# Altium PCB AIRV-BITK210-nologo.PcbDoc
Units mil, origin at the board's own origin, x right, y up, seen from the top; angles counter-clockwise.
Board outline 2559.06 x 1181.1 mil, 4 copper layers (Top Layer, GND, MidLayer1, Bottom Layer), stack 28.8 mil thick; 57 components, 83 nets, 310 pads, 220 vias.
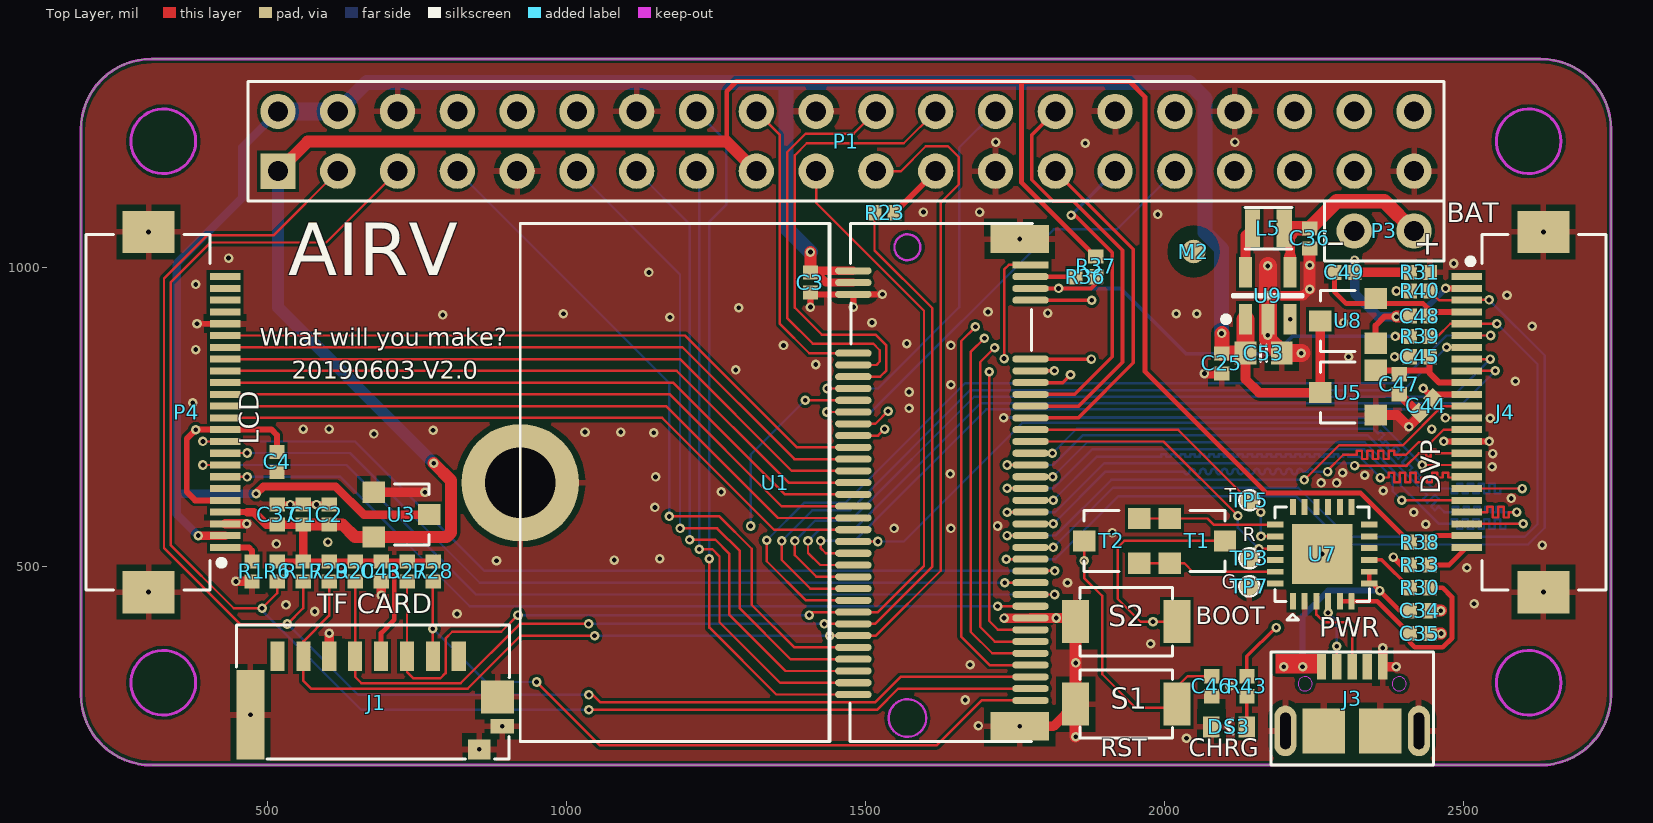
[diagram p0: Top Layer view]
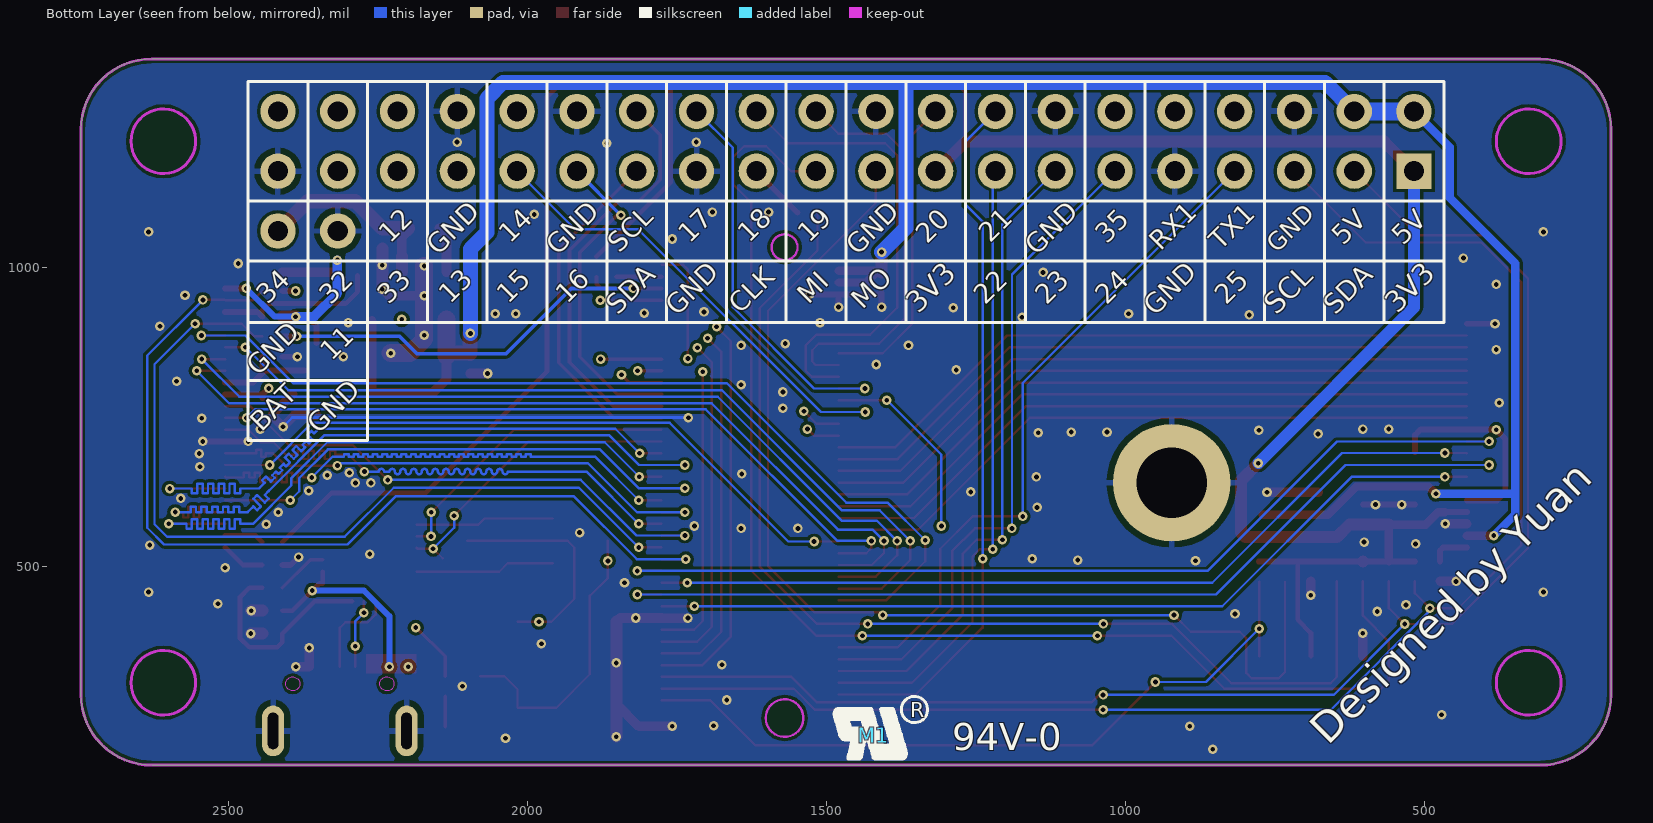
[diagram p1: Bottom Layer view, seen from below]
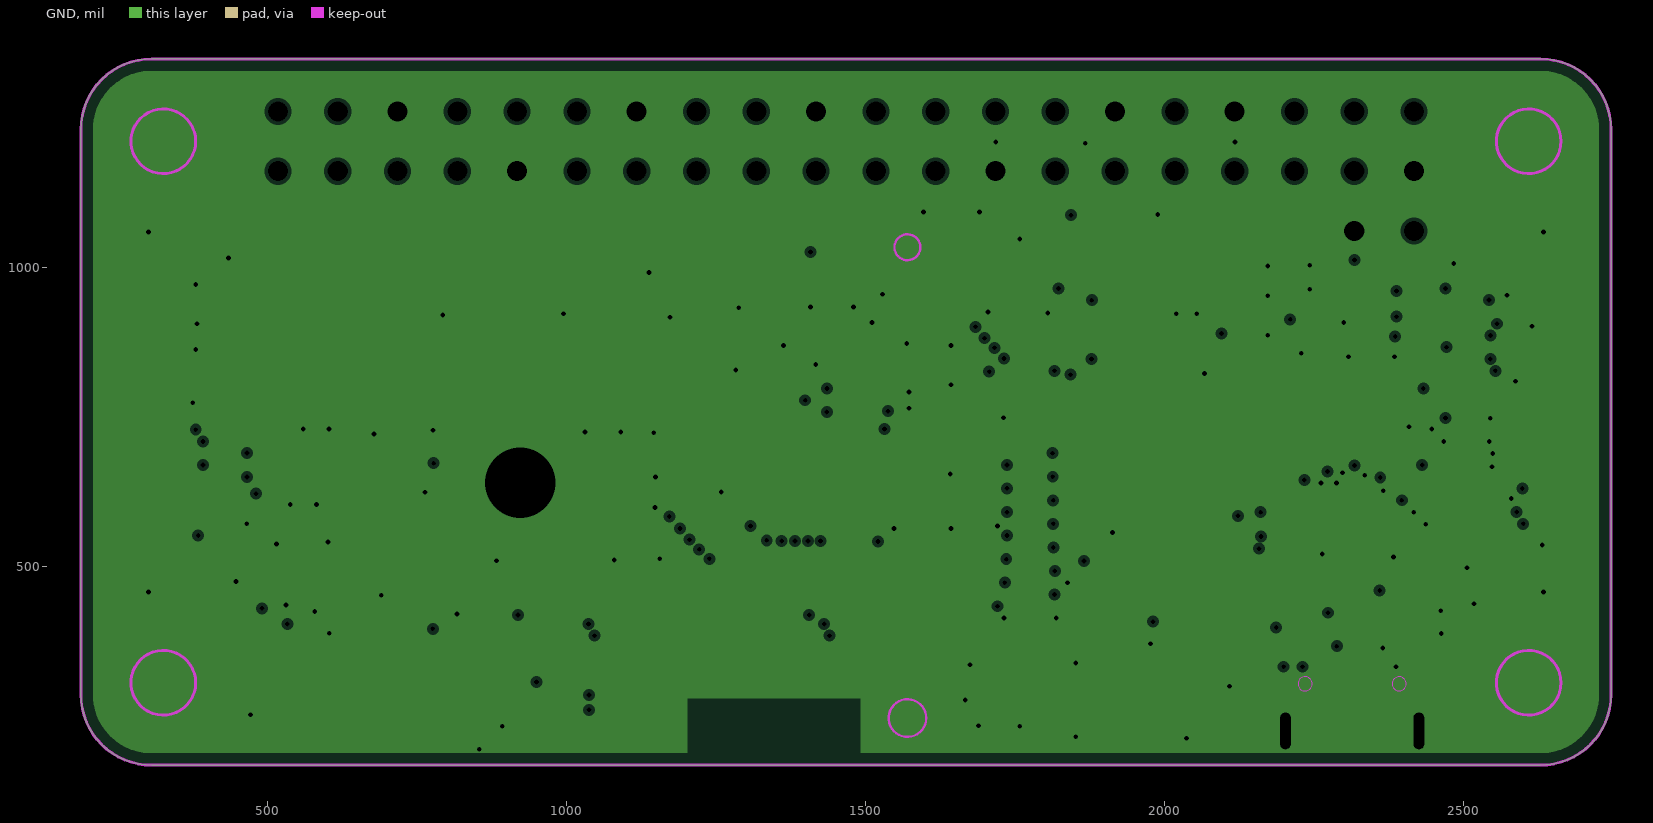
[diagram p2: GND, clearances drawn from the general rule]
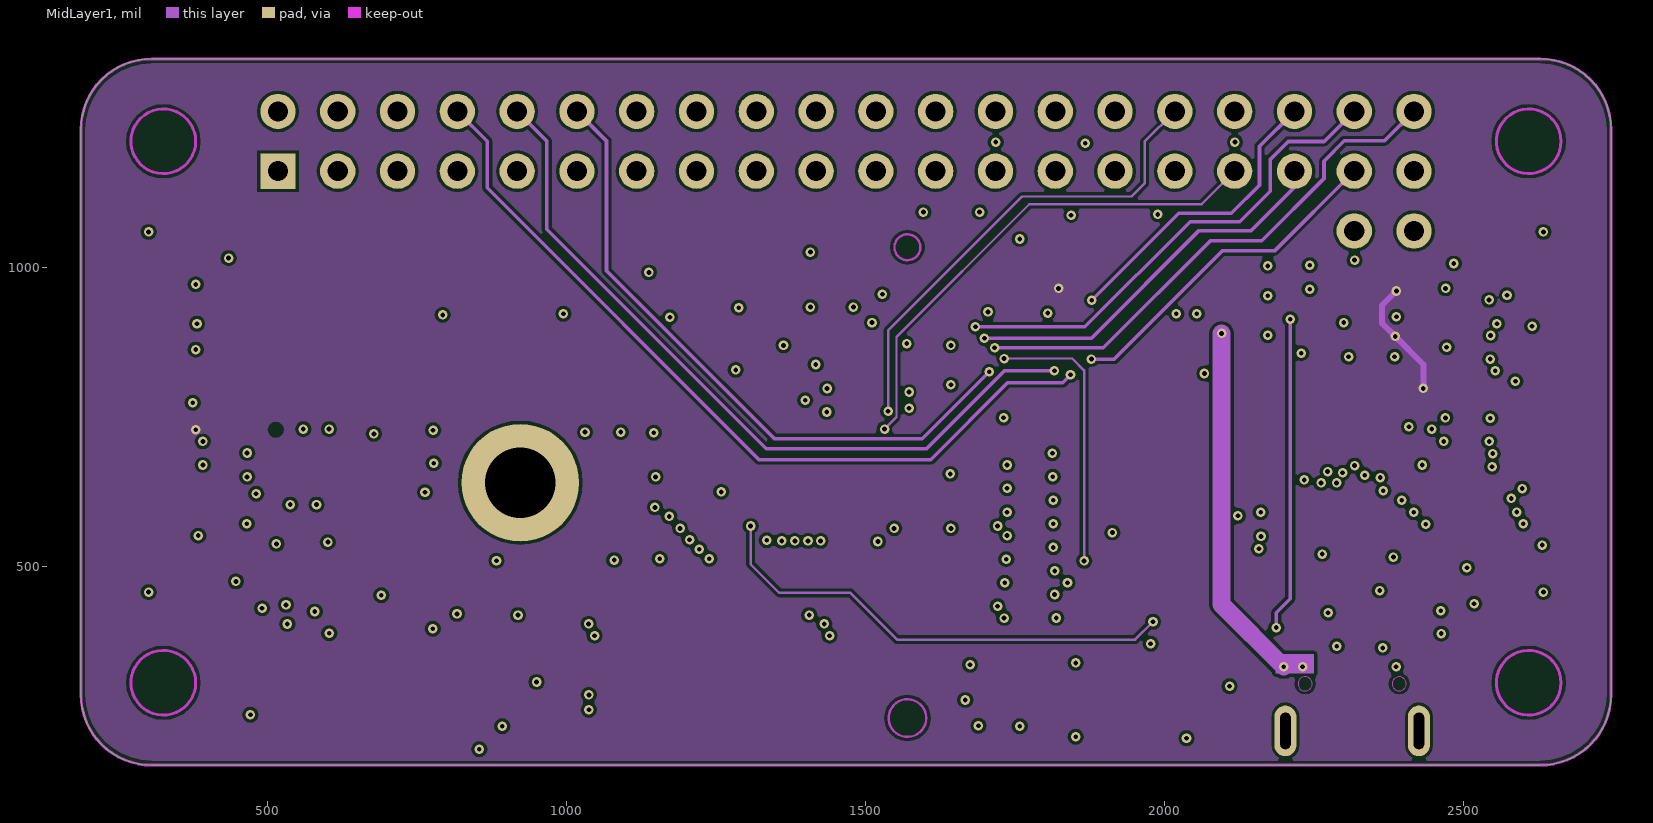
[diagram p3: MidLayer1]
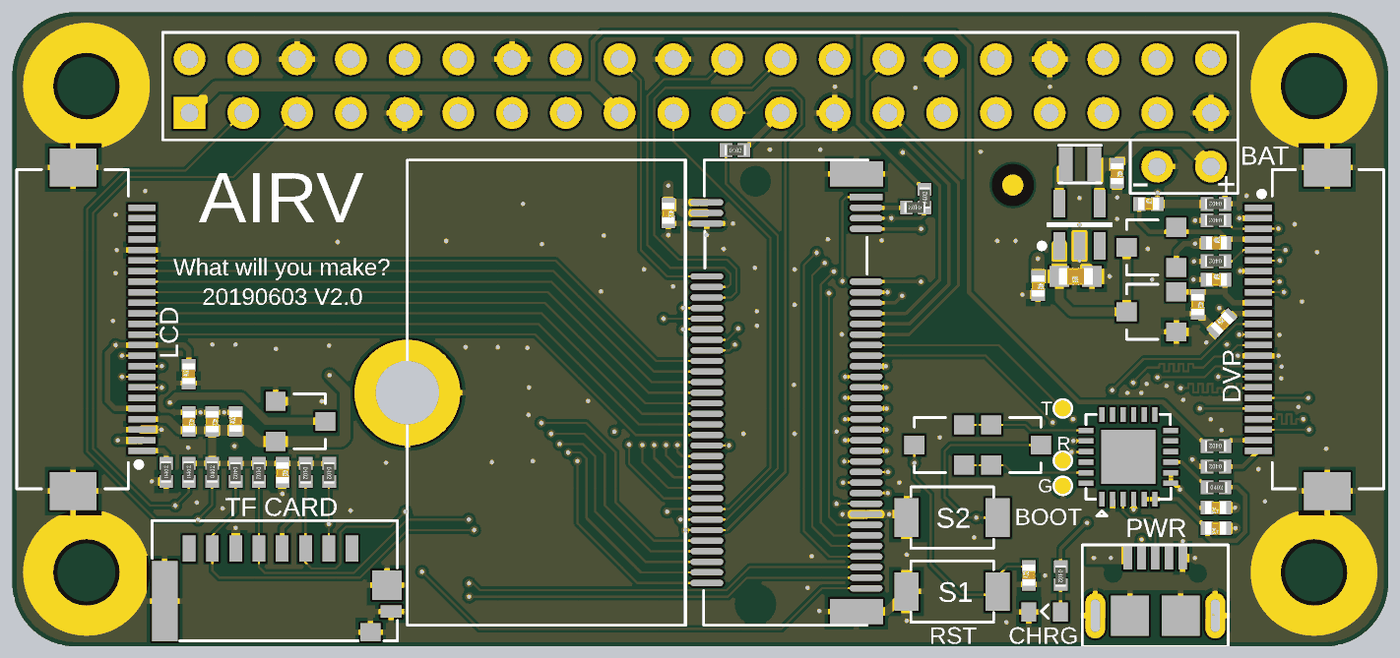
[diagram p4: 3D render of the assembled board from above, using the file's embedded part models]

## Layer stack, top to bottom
Top Solder: solder mask 0.4, Solder Resist, Dk 3.5
Top Layer: signal copper 1.4
Dielectric1: core 7.6, FR-4, Dk 4.8
GND: plane copper 1.4, net GND
Dielectric3: prepreg 8, FR-4, Dk 4.8
MidLayer1: signal copper 1.4
Dielectric2: core 7.6, FR-4, Dk 4.8
Bottom Layer: signal copper 1.4
Bottom Solder: solder mask 0.4, Solder Resist, Dk 3.5

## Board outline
188,285.11 ccw(c306.11,285.11) 306.11,167 2628.94,167 ccw(c2628.94,285.11) 2747.06,285.11 2747.06,1229.99 ccw(c2628.94,1229.99) 2628.94,1348.1 306.11,1348.1 ccw(c306.11,1229.99) 188,1229.99

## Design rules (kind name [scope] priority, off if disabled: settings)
AssemblyTestPointUsage [All] p1 off:
AssemblyTestpoint [All] p1 off: testpointundercomponent=TRUE minsize=40 maxsize=100 preferedsize=60 minholesize=0 maxholesize=40 preferedholesize=32 testpointgrid=1 usegrid=TRUE gridtolerance=0.01 allowsidetop=TRUE allowsidebottom=TRUE
Clearance Clearance_Polygon [InPolygon] p1: gap=5
Clearance [All] p2: gap=4
ComponentClearance [All] p1 off: gap=1 collisioncheckmode=3 verticalgap=1 showdistances=FALSE
DiffPairsRouting [All] p1: maxlimit=20 minlimit=4 mostfreqgap=5 toplayer_minwidth=4 toplayer_maxwidth=4 toplayer_prefwidth=4 midlayer1_minwidth=4 midlayer1_maxwidth=4 midlayer1_prefwidth=4 bottomlayer_minwidth=4 bottomlayer_maxwidth=4 bottomlayer_prefwidth=4 maxuncoupledlength=3000
FabricationTestPointUsage TestPointUsage [All] p1 off: valid=0 allowmultiple=FALSE
FabricationTestpoint Testpoint [(IsPad And (OnTopLayer Or OnBottomLayer))] p1 off: side=3 testpointundercomponent=TRUE minsize=40 maxsize=100 preferedsize=60 minholesize=0 maxholesize=40 preferedholesize=32 testpointgrid=1 allowsidetop=TRUE allowsidebottom=TRUE usegrid=TRUE gridtolerance=0.01
Height [All] p1 off: minheight=0 maxheight=1000 prefheight=500
HoleSize [All] p1: absolutevalues=TRUE maxlimit=150 minlimit=1 maxpercent=80.000 minpercent=20.000
MinimumSolderMaskSliver [All] p1 off: minsoldermaskwidth=1
PlaneClearance [All] p1: clearance=6
PlaneConnect [All] p1: planeconnectstyle=Direct reliefexpansion=20 reliefentries=4 reliefconductorwidth=25 reliefairgap=10
PolygonConnect PolygonConnect_1 [All vs IsPad] p1: connectstyle=Relief reliefconductorwidth=10 reliefentries=4 polygonreliefangle="90 Angle" airgapwidth=10
PolygonConnect PolygonConnect_isvia [All vs IsVia] p2: connectstyle=Direct reliefconductorwidth=10 reliefentries=4 polygonreliefangle="90 Angle" airgapwidth=10
PolygonConnect [All] p3: connectstyle=Direct reliefconductorwidth=8 reliefentries=4 polygonreliefangle="90 Angle" airgapwidth=10
RoutingVias [All] p1: holewidth=8 width=16 viastyle="Through Hole" minholewidth=8 minwidth=16 maxholewidth=100 maxwidth=100
ShortCircuit [InNet('WIFI') vs InNet('GND')] p1 off: allowed=FALSE
SilkToSilkClearance [All] p1: silktosilkclearance=0
SilkToSolderMaskClearance SilkscreenOverComponentPads [IsPad] p1: minsilkscreentomaskgap=0 clearancetoexposedcopper=TRUE
SolderMaskExpansion [All] p1: expansion=4
Width [All] p1: maxlimit=100 minlimit=4 preferedwidth=5
16 further rules are at their usual default settings.

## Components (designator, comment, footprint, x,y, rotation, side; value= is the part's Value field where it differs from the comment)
C1 "0.1uF" C0402 559.63,586 r270 top
C2 "10uF" C0402 603.16,586 r90 top
C3 "10uF" C0402 1408,974 r270 top
C4 "0.1uF" C0402 516,674 r90 top
C25 "10uF" C0402 2096,839 r270 top
C34 "10uF" C0402 2427,425.25 r180 top
C35 "10uF" C0402 2427,387 r180 top
C36 "10uF" C0402 2243,1048 r270 top
C37 "0.1uF" C0402 516.11,586 r270 top
C43 "0.1uF" C0402 690.21,491 r270 top
C44 "0.1uF" C0402 2438,768.27 r45 top
C45 "0.1uF" C0402 2427,850 r0 top
C46 "0.1uF" C0402 2079,299 r90 top
C47 "10uF" C0402 2393,804 r270 top
C48 "0.1uF" C0402 2427,918 r0 top
C49 "10uF" C0402 2301,991 r0 top
C53 "22uF" C0603 2166,856 r180 top
DS3 "LED" LED0603 2108,231 r180 top
J1 "TF" TFCARD473092651 676.19,289.05 r180 top locked
J3 "MICRO_USB" MICROUSB 2313.98,261.49 r0 top locked
J4 "OV2640" FFC/SM0.5-2H24-OV5640 2569.89,757.55 r90 top locked
L5 "2.2uH" VLS2016 2174,1065 r0 top
M1 "mark" ZY_UR-3X2 1421,217 r180 bottom
M2 "mark" MARKER-C 2049,1026 r0 top
P1 "Header 20X2" HDR2X20 517.53,1160.31 r0 top locked
P3 "Header 2 RUN" HDR1X2 2417.53,1060.31 r180 top locked
P4 "JLT24100B" FFC/SM0.5-2H24-LCD 365.17,757.55 r270 top locked
R1 "100R" R0402 474,491 r90 top
R6 "2.2K" R0402 516.11,491 r90 top
R17 "2.2K" R0402 559.63,491 r90 top
R20 "10K" R0402 646.68,491 r270 top
R23 "22R" R0402 1532,1091 r0 top
R27 "10K" R0402 733.74,491 r270 top
R28 "10K" R0402 777.26,491 r270 top
R29 "10K" R0402 603.16,491 r270 top
R30 "10K" R0402 2427,463.5 r0 top
R31 "0R" R0402 2427,991 r180 top
R33 "NC" R0402 2427,501.75 r180 top
R36 "0R" R0402 1868,984 r180 top
R37 "NC" R0402 1885,1001 r90 top
R38 "NC" R0402 2427,540 r180 top
R39 "2K" R0402 2427,884 r180 top
R40 "2K" R0402 2427,960 r180 top
R43 "1K" R0402 2138,299 r270 top
S1 "SW-BUTTON" MINIBUTTON 1936,269 r0 top
S2 "SW-BUTTON" MINIBUTTON 1936.46,407 r180 top
T1 "SI2302" SOT23 2055,542 r270 top locked
T2 "SI2302" SOT23 1912,542 r90 top locked
TP3 "TEST POINT" TEST-POINT 2142,513 r90 top
TP5 "TEST POINT" TEST-POINT 2142,610 r90 top
TP7 "TEST POINT" TEST-POINT 2142,466 r90 top
U1 "BITK210" NGFF_M_2-AKEY-K210 1349.42,639.44 r270 top locked
U3 "XC6206-3.3" SOT23 724,586 r270 top locked
U5 "XC6206-1.2" SOT23 2307,790 r90 top
U7 "CP2104" QFN24 2264,520 r90 top locked
U8 "XC6206-2.8" SOT23 2307,910 r90 top
U9 "ETA6093" SOT23-5 2173,952 r90 top

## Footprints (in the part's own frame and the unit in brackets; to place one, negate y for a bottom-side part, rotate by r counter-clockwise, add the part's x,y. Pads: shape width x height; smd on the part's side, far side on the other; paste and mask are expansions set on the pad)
C0402 [mm]
  rect 0.6x0.65 smd mask+0.051: 1(-0.425,0) 2(0.425,0)
  body extent -0.48,-0.3 0.52,0.3, height 0.2
C0603 [mm]
  rect 0.93x0.98 smd: 1(-0.77,0) 2(0.77,0)
  silkscreen extent -0.13,-0.35 0.13,0.35, body extent -0.8,-0.4 0.8,0.4, height 0.3
FFC/SM0.5-2H24-LCD [mm] "Connector; FH12 Series; 24 Position; 0.5mm Spaced Bottom Contact"
  rect 0.3x1.3 smd: 1(5.75,1.625) 2(5.25,1.625) 3(4.75,1.625) 4(4.25,1.625) 5(3.75,1.625) 6(3.25,1.625) 7(2.75,1.625) 8(2.25,1.625) 9(1.75,1.625) 10(1.25,1.625) 11(0.75,1.625) 12(0.25,1.625) 13(-0.25,1.625) 14(-0.75,1.625) 15(-1.25,1.625) 16(-1.75,1.625) 17(-2.25,1.625) 18(-2.75,1.625) 19(-3.25,1.625) 20(-3.75,1.625) 21(-4.25,1.625) 22(-4.75,1.625) 23(-5.25,1.625) 24(-5.75,1.625)
  rect 1.8x2.2 smd: P0(-7.65,-1.625) P0(7.65,-1.625)
  silkscreen extent -7.55,-4.29 7.55,1.6
FFC/SM0.5-2H24-OV5640 [mm] "Connector; FH12 Series; 24 Position; 0.5mm Spaced Bottom Contact"
  rect 0.3x1.3 smd: 1(5.75,1.625) 2(5.25,1.625) 3(4.75,1.625) 4(4.25,1.625) 5(3.75,1.625) 6(3.25,1.625) 7(2.75,1.625) 8(2.25,1.625) 9(1.75,1.625) 10(1.25,1.625) 11(0.75,1.625) 12(0.25,1.625) 13(-0.25,1.625) 14(-0.75,1.625) 15(-1.25,1.625) 16(-1.75,1.625) 17(-2.25,1.625) 18(-2.75,1.625) 19(-3.25,1.625) 20(-3.75,1.625) 21(-4.25,1.625) 22(-4.75,1.625) 23(-5.25,1.625) 24(-5.75,1.625)
  rect 1.8x2.2 smd: P0(-7.65,-1.625) P0(7.65,-1.625)
  silkscreen extent -7.55,-4.29 7.55,1.6
HDR1X2 [mm]
  round 1.5 hole 0.85: 1(0,0) 2(2.54,0)
  silkscreen extent -1.27,-1.27 3.81,1.27
HDR2X20 [mm]
  rect 1.5x1.5 hole 0.85: 1(0,0)
  round 1.5 hole 0.85: 2(0,2.54) 3(2.54,0) 4(2.54,2.54) 5(5.08,0) 6(5.08,2.54) 7(7.62,0) 8(7.62,2.54) 9(10.16,0) 10(10.16,2.54) 11(12.7,0) 12(12.7,2.54) 13(15.24,0) 14(15.24,2.54) 15(17.78,0) 16(17.78,2.54) 17(20.32,0) 18(20.32,2.54) 19(22.86,0) 20(22.86,2.54) 21(25.4,0) 22(25.4,2.54) 23(27.94,0) 24(27.94,2.54) 25(30.48,0) 26(30.48,2.54) 27(33.02,0) 28(33.02,2.54) 29(35.56,0) 30(35.56,2.54) 31(38.1,0) 32(38.1,2.54) 33(40.64,0) 34(40.64,2.54) 35(43.18,0) 36(43.18,2.54) 37(45.72,0) 38(45.72,2.54) 39(48.26,0) 40(48.26,2.54)
  silkscreen extent -1.27,-1.27 49.53,3.81
LED0603 [mm]
  rect 0.7x0.9 smd: A(-0.75,0) K(0.75,0)
  silkscreen extent -0.18,-0.34 0.15,0.3
MARKER-C [mm]
  round 1 smd paste-1.016 mask+0.5: 0(0,0)
  Top Layer pour cut-out: -1.109,0 -1.072,-0.287 -0.961,-0.555 -0.785,-0.785 -0.555,-0.961 -0.287,-1.072 0,-1.109 0,-1.109 0.287,-1.072 0.555,-0.961 0.785,-0.785 0.961,-0.555 1.072,-0.287 1.109,0 1.109,0 1.072,0.287 0.961,0.555 0.785,0.785 0.555,0.961 0.287,1.072 0,1.109 0,1.109 -0.287,1.072 -0.555,0.961 -0.785,0.785 -0.961,0.555 -1.072,0.287 -1.109,0
MICROUSB [mm] "MICROUSB"
  rect 0.4x1.1 smd: 1(-1.3,1.78) 2(-0.65,1.78) 3(0,1.78) 4(0.65,1.78) 5(1.3,1.78)
  oval 0.94x2.15 hole 0.45 slot 1.55 at 90 deg: 6(-2.835,-0.946) 7(2.835,-0.946)
  rect 1.8x1.9 smd: 8(-1.2,-0.946) 9(1.2,-0.946)
  Keep-Out Layer circle w0.025: c-2,1.054 r0.3
  Keep-Out Layer circle w0.025: c2,1.054 r0.3
  silkscreen extent -3.45,-2.4 3.45,2.4
MINIBUTTON [mil] "MINIBUTTON"
  rect 44.88x72.05 smd: 1(-84.42,0.08) 2(84.88,0.08)
  silkscreen extent -77,-57 77,57
NGFF_M_2-AKEY-K210 [mm] "NGFF_M_2"
  rect 1.2x2.5 smd: 0(-10.35,10.38) 0(10.35,10.38)
  round 5 hole 3: 0(0,-10.837)
  rect 0.3x1.55 smd: 1(-9.25,10.837)
  oval 0.3x1.55 smd: 2(-9,3.313) 3(-8.75,10.837) 4(-8.5,3.313) 5(-8.25,10.837) 6(-8,3.313) 7(-7.75,10.837) 16(-5.5,3.313) 17(-5.25,10.837) 18(-5,3.313) 19(-4.75,10.837) 20(-4.5,3.313) 21(-4.25,10.837) 22(-4,3.313) 23(-3.75,10.837) 24(-3.5,3.313) 25(-3.25,10.837) 26(-3,3.313) 27(-2.75,10.837) 28(-2.5,3.313) 29(-2.25,10.837) 30(-2,3.313) 31(-1.75,10.837) 32(-1.5,3.313) 33(-1.25,10.837) 34(-1,3.313) 35(-0.75,10.837) 36(-0.5,3.313) 37(-0.25,10.837) 38(0,3.313) 39(0.25,10.837) 40(0.5,3.313) 41(0.75,10.837) 42(1,3.313) 43(1.25,10.837) 44(1.5,3.313) 45(1.75,10.837) 46(2,3.313) 47(2.25,10.837) 48(2.5,3.313) 49(2.75,10.837) 50(3,3.313) 51(3.25,10.837) 52(3.5,3.313) 53(3.75,10.837) 54(4,3.313) 55(4.25,10.837) 56(4.5,3.313) 57(4.75,10.837) 58(5,3.313) 59(5.25,10.837) 60(5.5,3.313) 61(5.75,10.837) 62(6,3.313) 63(6.25,10.837) 64(6.5,3.313) 65(6.75,10.837) 66(7,3.313) 67(7.25,10.837) 68(7.5,3.313) 69(7.75,10.837) 70(8,3.313) 71(8.25,10.837) 72(8.5,3.313) 73(8.75,10.837) 74(9,3.313) 75(9.25,10.837)
  Keep-Out Layer circle w0.1: c10,5.61 r0.8
  Keep-Out Layer circle w0.1: c-10,5.61 r0.55
  silkscreen extent -11,-10.84 11,10.92
QFN24 [mm]
  rect 0.7x0.25 smd: 1(-2,1.25) 2(-2,0.75) 3(-2,0.25) 4(-2,-0.25) 5(-2,-0.75) 6(-2,-1.25) 13(2,-1.25) 14(2,-0.75) 15(2,-0.25) 16(2,0.25) 17(2,0.75) 18(2,1.25)
  rect 0.25x0.7 smd: 7(-1.25,-2) 8(-0.75,-2) 9(-0.25,-2) 10(0.25,-2) 11(0.75,-2) 12(1.25,-2) 19(1.25,2) 20(0.75,2) 21(0.25,2) 22(-0.25,2) 23(-0.75,2) 24(-1.25,2)
  rect 2.55x2.55 smd: 25(0,0)
  silkscreen extent -2.79,-2.01 2.01,2.01
R0402 [mm]
  rect 0.6x0.65 smd mask+0.051: 1(-0.425,0) 2(0.425,0)
  body extent -0.47,-0.25 0.53,0.25, height 0.35
SOT23 [mm] "SOT-23; 3 Leads; Body 3.0 x 2.5 mm, inc. leads (LxW max)"
  rect 0.9x0.95 smd: 1(-0.95,-1.175) 2(0.95,-1.175) 3(0,1.175)
  silkscreen extent -1.3,-0.3 1.3,1.18
SOT23-5 [mm] "SOT23, 5-Leads, Body 3.0x2.6mm (max), Pitch 0.95mm, IPC Medium Density"
  rect 1.3x0.55 smd: 1(-1,0.95) 2(-1,0) 3(-1,-0.95) 4(1,-0.95) 5(1,0.95)
  silkscreen extent -1.12,-1.5 0.05,1.9, body extent -0.7,-1.5 0.7,1.5, height 1.1
TEST-POINT [mil]
  round 30 smd paste-15.75: 1(0,0)
  silkscreen extent -17,-17 17,17
TFCARD473092651 [mm] "TFCARD473092651"
  rect 0.6x1.25 smd: 1(-3.65,-1.525) 2(-2.55,-1.525) 3(-1.45,-1.525) 4(-0.35,-1.525) 5(0.75,-1.525) 6(1.85,-1.525) 7(2.95,-1.525) 8(4.05,-1.525)
  rect 1.2x3.8 smd: G1(5.2,0.96)
  rect 1.4x1.4 smd: G2(-5.3,0.2)
  rect 1x0.6 smd: G3(-5.5,1.45)
  rect 0.95x0.85 smd: G4(-4.525,2.425)
  silkscreen extent -5.8,-2.85 5.8,2.84
VLS2016 [mm] "VLS2016"
  rect 0.65x1.6 smd: 1(0.675,0) 2(-0.675,0)
  silkscreen extent -1,-0.89 1,0.89
ZY_UR-3X2 [mil]
  silkscreen extent -67,-40 90,65

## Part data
C1 C2 C3 C4 C25 C34 C35 C36 C37 C43 C44 C45 C46 C47 C48 C49 C53: library part CAP, "普通小电容"
J1: library part TF_473092651
J4: library part OV5640, "Header, 24-Pin"
L5: library part L, "普通电感"
P1: "Header, 20-Pin, Dual row"
P3: library part "Header 2", "Header, 2-Pin"
R1 R6 R17 R20 R23 R27 R28 R29 R30 R31 R33 R36 R37 R38 R39 R40 R43: library part RES, "普通电阻"
T1 T2: library part MOS-N
TP3 TP5 TP7: library part TP, "Description"
U3 U5 U8: library part XC6206

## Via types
v1: diameter 16, hole 8, Top Layer to Bottom Layer, tented both sides, 220 vias

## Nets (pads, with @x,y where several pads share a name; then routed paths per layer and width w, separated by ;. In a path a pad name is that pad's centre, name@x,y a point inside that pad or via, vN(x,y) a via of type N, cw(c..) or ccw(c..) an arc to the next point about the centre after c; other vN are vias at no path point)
AGND: C48.1 C49.2 J4.2 R31.2 U8.1 | length 465.1
  Top Layer w10: U8.1 2353.26,902.26 2368,917 v1(2388,917) ; v1(2470.24,964.24) J4.2
  Top Layer w16: C49.2@2318,991.27 C49.2 R31.2
  Top Layer w20: v1(2388,917) C48.1@2410.27,917
  Bottom Layer w10: v1(2388,917) 2423,917 v1(2470.24,964.24)
  Bottom Layer w16: v1(2318,1011.73) 2318,956 2357,917 v1(2388,917)
AVDD2V8: C48.2 C49.1 J4.4 U8.2 | length 275.8
  Top Layer w8: C49.1@2284.27,985.74 2284.27,958.73 2304,939 2433,939 2443.73,928.27 C48.2@2443.73,917
  Top Layer w10: C48.2@2443.73,917 2451.61,924.87 J4.4
BAT: C36.1 L5.1 P3.1 U9.4 | length 397.8
  Top Layer w16: U9.4 2210.57,991.54 L5.1@2210.57,1065 ; 2210.4,1017.59 L5.1@2210.4,1055.17
  Top Layer w20: U9.4 2210.4,1017.59
  Top Layer w24: L5.1 L5.1@2210.4,1055.17 ; L5.1@2210.57,1065 2210.84,1064.73 C36.1 2288.27,1110 2367.83,1110 P3.1
BOOT_KEY0: S2.1 T1.3 U1.24 | length 1510.7
  Top Layer w4: v1(1399.24,777.24) U1.24 ; S2.1@2016.88,406.92 v1(1981,406.92) 1960.08,406.92 1922,445 1922,531 1933,542 T1.3
  MidLayer1 w4: v1(1308,567) 1308,503 1356,455 1475,455 1553,377 1951.08,377 v1(1981,406.92)
  Bottom Layer w4: v1(1308,567) 1308,686 v1(1399.24,777.24)
DTR: T1.2 T2.1 U7.23 | length 232.9
  Top Layer w4: T2.1 2033.4,504.6 2047.53,490.47 U7.23
DVP-Y2: J4.19 U1.33 | length 1237.5
  Top Layer w4: U1.33 v1(1812.65,688.65) ; J4.19 v1(2598.6,629.6)
  Bottom Layer w4: v1(1812.65,688.65) 1853.5,729.5 2349.5,729.5 2354,725 2357.18,721.82 2361.42,726.06 2367.79,719.7 2363.55,715.45 2359.3,711.21 2365.67,704.85 2369.91,709.09 2376.27,702.73 2372.03,698.48 2378.4,692.12 2382.64,696.36 2386.88,700.6 2393.24,694.24 2389,690 2384.76,685.76 2391.12,679.39 2395.37,683.63 2399.61,687.88 2405.97,681.51 2401.73,677.27 2397.49,673.03 2403.85,666.66 2408.09,670.91 2414.46,664.54 2410.22,660.3 2416.58,653.94 2420.82,658.18 2427.19,651.81 2422.94,647.57 2429.31,641.21 2433.55,645.45 2437.79,649.69 2444.16,643.33 2439.91,639.09 2444,635 2449.4,629.6 2467,629.6 2471.5,629.6 2480.5,629.6 2480.5,621.6 2489.5,621.6 2489.5,629.6 2489.5,637.6 2498.5,637.6 2498.5,629.6 2498.5,621.6 2507.5,621.6 2507.5,629.6 2507.5,637.6 2516.5,637.6 2516.5,629.6 2516.5,621.6 2525.5,621.6 2525.5,629.6 2525.5,637.6 2534.5,637.6 2534.5,629.6 2534.5,621.6 2543.5,621.6 2543.5,629.6 2543.5,637.6 2552.5,637.6 2552.5,629.6 2552.5,621.6 2561.5,621.6 2561.5,629.6 2566,629.6 v1(2598.6,629.6)
DVP-Y3: J4.21 U1.35 | length 1264.7
  Top Layer w4: v1(1737,669) U1.35 ; J4.21 2535.73,590.23 2540.23,590.23 2540.23,599.23 2549.23,599.23 2549.23,590.23 2549.23,581.23 2558.23,581.23 2558.23,590.23 2558.23,599.23 2567.23,599.23 2567.23,590.23 2567.23,581.23 2576.23,581.23 2576.23,590.23 2585.23,590.23 v1(2589.23,590.23)
  Bottom Layer w4: v1(1737,669) 1813.94,669 ; 1813.97,668.97 1864,719 2339.46,719 2428.73,629.73 2433.23,625.23 2439.59,618.87 2433.23,612.5 2439.59,606.14 2445.95,612.5 2452.32,618.87 2458.68,612.5 2452.32,606.14 2445.95,599.77 2452.32,593.41 2458.68,599.77 2465.05,593.41 2468.23,590.23 2473.5,590.23 2482.5,590.23 2482.5,599.23 2491.5,599.23 2491.5,590.23 2500.5,590.23 2500.5,599.23 2509.5,599.23 2509.5,590.23 2518.5,590.23 2518.5,599.23 2527.5,599.23 2527.5,590.23 2536.5,590.23 2536.5,599.23 2545.5,599.23 2545.5,590.23 2554.5,590.23 2554.5,599.23 2563.5,599.23 2563.5,590.23 2572.5,590.23 2577,590.23 v1(2589.23,590.23)
DVP-Y4: J4.22 U1.37 | length 1166.1
  Top Layer w4: U1.37 v1(1813.28,649.28) ; J4.22@2505.46,571 J4.22 v1(2600,570.54)
  Bottom Layer w4: v1(1813.28,649.28) 1871,707 2335,707 2395,647 2395,635 2459.46,570.54 2476,570.54 2480.5,570.54 2480.5,578.54 2489.5,578.54 2489.5,570.54 2489.5,562.54 2498.5,562.54 2498.5,570.54 2498.5,578.54 2507.5,578.54 2507.5,570.54 2507.5,562.54 2516.5,562.54 2516.5,570.54 2516.5,578.54 2525.5,578.54 2525.5,570.54 2525.5,562.54 2534.5,562.54 2534.5,570.54 2534.5,578.54 2543.5,578.54 2543.5,570.54 2543.5,562.54 2552.5,562.54 2552.5,570.54 2552.5,578.54 2561.5,578.54 2561.5,570.54 2561.5,562.54 2570.5,562.54 2570.5,570.54 2573,570.54 v1(2600,570.54)
DVP-Y5: J4.20 U1.39 | length 883.6
  Top Layer w4: v1(1737,630) 1775.68,630 U1.39 ; v1(2397,610) 2505.83,610 J4.20
  Bottom Layer w4: v1(1737,630) 1813.2,630 1813.6,629.6 1879,695 2334,695 2382,647 2382,625 v1(2397,610)
DVP-Y6: J4.18 U1.41 | length 1079.1
  Top Layer w4: U1.41 v1(1814.09,609.91) ; v1(2361,648) 2371,648 2375.5,648 2375.5,656 2384.5,656 2384.5,648 2384.5,640 2393.5,640 2393.5,648 2393.5,656 2402.5,656 2402.5,648 2402.5,640 2411.5,640 2411.5,648 2411.5,656 2420.5,656 2420.5,648 2420.5,640 2429.5,640 2429.5,648 2438.5,648 2438.5,640 2447.5,640 2447.5,648 2447.5,656 2456.5,656 2456.5,648 2465.5,648 2465.5,656 2474.5,656 2474.5,648 2478,648 2504.63,648 J4.18
  Bottom Layer w4: v1(1814.09,609.91) 1887.17,683 1991,683 1995,683 1995,687 2003,687 2003,683 2011,683 2011,687 2019,687 2019,683 2027,683 2027,687 2035,687 2035,683 2043,683 2043,687 2051,687 2051,683 2059,683 2059,687 2067,687 2067,683 2075,683 2075,687 2083,687 2083,683 2091,683 2091,687 2099,687 2099,683 2107,683 2107,687 2115,687 2115,683 2123,683 2123,687 2131,687 2131,683 2139,683 2139,687 2147,687 2147,683 2155,683 2155,687 2163,687 2163,683 2171,683 2171,687 2179,687 2179,683 2187,683 2187,687 2195,687 2195,683 2203,683 2203,687 2211,687 2211,683 2219,683 2219,687 2227,687 2227,683 2235,683 2235,687 2243,687 2243,683 2251,683 2251,687 2259,687 2259,683 2267,683 2267,687 2275,687 2275,683 2283,683 2283,687 2291,687 2291,683 2299,683 2299,687 2307,687 2307,683 2315,683 2319,683 2326,683 v1(2361,648)
DVP-Y7: J4.16 U1.43 | length 876.3
  Top Layer w4: v1(1737,590) 1775.85,590 U1.43 ; v1(2318,668) 2405,668 2425.65,688.65 2429.65,688.65 2437.65,688.65 2437.65,682.65 2445.65,682.65 2445.65,688.65 2445.65,694.65 2453.65,694.65 2453.65,688.65 2456,688.65 J4.16
  Bottom Layer w4: v1(1737,590) 1817,590 1899,672 2314,672 v1(2318,668)
DVP-Y8: J4.14 U1.45 | length 1012.4
  Top Layer w4: U1.45 v1(1814,570.54) ; v1(2273,658) 2273,660 2299,686 2303.5,686 2312.5,686 2321.5,686 2321.5,693 2330.5,693 2330.5,686 2330.5,679 2339.5,679 2339.5,686 2339.5,693 2348.5,693 2348.5,686 2348.5,679 2357.5,679 2357.5,686 2357.5,693 2366.5,693 2366.5,686 2366.5,679 2375.5,679 2375.5,686 2375.5,693 2384.5,693 2384.5,686 2390,686 2404,686 2425,707 2446,707 2467.02,728.02 J4.14
  Bottom Layer w4: v1(1814,570.54) 1901.46,658 2024,658 2033,658 ccw(c2037.5,658) 2042,658 cw(c2046.5,658) 2051,658 ccw(c2055.5,658) 2060,658 cw(c2064.5,658) 2069,658 ccw(c2073.5,658) 2078,658 cw(c2082.5,658) 2087,658 ccw(c2091.5,658) 2096,658 cw(c2100.5,658) 2105,658 ccw(c2109.5,658) 2114,658 cw(c2118.5,658) 2123,658 ccw(c2127.5,658) 2132,658 cw(c2136.5,658) 2141,658 ccw(c2145.5,658) 2150,658 cw(c2154.5,658) 2159,658 ccw(c2163.5,658) 2168,658 cw(c2172.5,658) 2177,658 ccw(c2181.5,658) 2186,658 cw(c2190.5,658) 2195,658 ccw(c2199.5,658) 2204,658 cw(c2208.5,658) 2213,658 ccw(c2217.5,658) 2222,658 cw(c2226.5,658) 2231,658 2240,658 cw(c2244.5,658) 2249,658 2258,658 v1(2273,658)
DVP-Y9: J4.12 U1.47 | length 897.7
  Top Layer w4: v1(1737,551) 1775.94,551 U1.47 ; v1(2234,644) 2292,702 2399,702 2464.39,767.39 J4.12
  Bottom Layer w4: v1(1737,551) 1818,551 1911,644 v1(2234,644)
DVP_HSYNC: J4.9 U1.52 | length 1419.1
  Top Layer w4: v1(1404,542) 1404,522 1424.35,501.65 U1.52 ; J4.9 v1(2553.45,826.45)
  Bottom Layer w4: v1(1404,542) 1423,561 1481,561 1692,772 2499,772 v1(2553.45,826.45)
DVP_PCLK: J4.17 U1.48 | length 1137.5
  Top Layer w4: U1.48 v1(1520.98,541.02) ; v1(2431.06,669) J4.17
  Bottom Layer w4: v1(1520.98,541.02) 1564.02,541.02 1762.5,739.5 2360.5,739.5 v1(2431.06,669)
DVP_PWDN: J4.8 U1.54 | length 1465.1
  Top Layer w4: v1(1382,542) 1382,518 1418.04,481.96 U1.54 ; J4.8 v1(2545.13,846.13)
  Bottom Layer w4: v1(1382,542) 1416,576 1475,576 1682,783 2482,783 v1(2545.13,846.13)
DVP_RST: J4.6 U1.58 | length 1602.4
  Top Layer w4: v1(1335,543) 1335,508 1400.41,442.59 U1.58 ; J4.6 v1(2545.5,885.5)
  Bottom Layer w4: v1(1335,543) 1398,606 1467,606 1667,806 2392.2,806 2471.7,885.5 v1(2545.5,885.5) v1@2543.01,888
DVP_SCL: J4.5 R39.1 U1.49 | length 1416.4
  Top Layer w4: U1.49 v1(1814.17,531.17) ; R39.1 2457,884 2478.19,905.19 J4.5 v1(2556.19,905.19)
  Bottom Layer w4: v1(1814.17,531.17) 1914,631 2224,631 2306,549 2603,549 2624,570 2624,837.38 v1(2556.19,905.19)
DVP_SDA: J4.3 R40.1 U1.51 | length 1555.3
  Top Layer w4: v1(1735.51,511.49) U1.51 ; R40.1 2459.17,944.56 J4.3 2506.36,945 v1(2543,945)
  Bottom Layer w4: v1(1735.51,511.49) 1817.49,511.49 1923,617 2220,617 2301,536 2608,536 2636,564 2636,852 v1(2543,945)
DVP_VSYNC: J4.7 U1.56 | length 1451.8
  Top Layer w4: v1(1360,542) 1360,510 1407.72,462.28 U1.56 ; v1(2472,866) 2505.73,866 J4.7
  Bottom Layer w4: v1(1360,542) 1411,593 1474,593 1675,794 2400,794 v1(2472,866)
DVP_XCLK: J4.13 U1.50 | length 1248.4
  Top Layer w4: v1(1425,542) 1425,530 1433.67,521.33 U1.50 ; v1(2470,747.71) J4.13
  Bottom Layer w4: v1(1425,542) 1482,542 1702,762 2455.71,762 v1(2470,747.71)
GND: C1.1 C2.2 C3.2 C4.1 C25.2 C34.1 C35.1 C36.2 C37.1 C43.2 C44.1 C45.1 C46.1 C47.2 C53.1 DS3.K J1.6 J1.G1 J1.G2 J1.G3 J1.G4 J3.5 J3.6 J3.7 J3.8 J3.9 J4.15 J4.P0 P1.6 P1.9 P1.14 P1.20 P1.25 P1.30 P1.34 P1.39 P3.2 P4.3 P4.20 P4.P0 R1.1 R31.1 R33.2 S1.1 S2.2 TP7.1 U1.0 U1.6 U1.61 U3.1 U5.1 U7.2 U7.25 U9.2 | length 2339.9
  Top Layer w10: v1(382.19,905.19) P4.20 ; C37.1 C1.1 C2.2 ; v1(1408,933) C3.2 ; C3.2@1410.87,954.4 U1.6 ; v1(1479.84,933) U1.6 ; v1(1528.4,954.4) U1.6 ; v1(2383,515) 2396.25,501.75 R33.2 ; v1(2385,850) C45.1 ; v1(2467.34,708.34) J4.15 v1(2543.34,708.34)
  Top Layer w16: P4.3 v1(465.32,570.54) ; v1(447.27,474.27) R1.1 ; J1.6 v1(603.36,387.64) ; U3.1 v1(763.4,623.4) ; v1(690.21,451.21) C43.2 ; v1(1732,413) 1775.83,413 1776.08,412.75 U1.61 v1(1819,413.06) 1845.44,413.06 S2.2 ; v1(1758.08,231.96) 1814.46,231.96 S1.1 ; v1(2067,822) C25.2@2095.73,822 ; v1(2173,952) 2232.05,952 v1(2243,962.94) ; U5.1 2389.4,752.6 v1(2409,733) 2426.17,750.17 2426.17,754.1 C47.2 ; v1(2365.17,363) J3.5 v1(2387.58,331.58)
  Top Layer w20: v1(1851.58,214.58) S1.1 v1(1851.58,338) S2.2 ; v1(2243,962.94) C36.2 ; C35.1 v1(2463,387) ; C34.1 v1(2462.25,425.25)
  Top Layer w30: v1(2173,1002) v1(2173,952) U9.2 v1(2173,886) 2173,879.32 C53.1 v1(2229,856)
  Bottom Layer w4: 2394,748 v1(2409,733)
  Bottom Layer w5: v1(1731,748) 2394,748
  other v1: 854.34,193.58 2037,212 892.73,231.97 1689,233 471.47,251.26 1667,276 2109,299 1675,335 1977,370 817,420 579,424 531,435 2518,437 301.19,456.37 2633.87,456.37 1838,472 2506,497 883,509 1080,510 1156,512 2264,520 2632,535 515,537 601,540 1913,556 1548,563 1643,563 1721,567 2437,570 2417,590 1148,598 538,602.73 582,602.73 2580,613 1259,624 2366,626 2262,639 2288,639 1149,649 2335,652 1642,654 2298,656 2548,666 2549,688 678,721 1146,723 1031,724 1091,724 777,727 560,729 603,729 2447,729 2545,747 1573,764 375,773 1573,791 1643,803 2587,809 1283,828 1417,837 2308,850 380,862 1363,869 1643,869 1569,872 2615,901 1511,907.16 2300,907.16 1173,916 793,920 995,922 2020,922 2054,922 1805,923 1705,925 1288,932 2573,953 380,971 1138,991 2243,1003 2484,1006 435,1015 1758.08,1046.92 301.19,1058.73 2633.87,1058.73 1989,1088 1597,1092 1691,1092 1867.53,1207 1718,1209 2118,1209
I2C_SCL: P1.5 R6.1 U1.73 | length 2520.2
  Top Layer w4: R6.1 516.11,454.37 v1(491,429.27) 443.73,429.27 338,535 338,974 405,1041 598.22,1041 P1.5 ; v1(1037.5,259.5) 1519.5,259.5 1554.95,294.95 U1.73
  Bottom Layer w4: v1(491,429.27) 491,425.46 656.96,259.5 v1(1037.5,259.5)
I2C_SDA: P1.3 R17.1 U1.71 | length 2471.5
  Top Layer w4: 559.53,429.27 v1(533.26,403) 454,403 327,530 327,981 399,1053 510.22,1053 P1.3 ; 559.63,429.37 R17.1 ; v1(1037.5,284.5) 1044.5,284.5 1057,272 1516,272 1558.64,314.64 U1.71
  Bottom Layer w4: v1(533.26,403) 651.76,284.5 v1(1037.5,284.5)
I2S_BCK: P1.12 U1.63 | length 1581.7
  Top Layer w4: v1(1707,825) 1707,408 1721.62,393.38 U1.63
  MidLayer1 w6: P1.12 1067,1210.83 1067,994 1348,713 1595,713 v1(1707,825)
I2S_DI: P1.38 U1.69 | length 1477.6
  Top Layer w4: v1(1684,900) 1660,876 1660,382 1707.68,334.32 U1.69
  MidLayer1 w6: v1(1684,900) 1867,900 2043,1076 2126,1076 2177,1127 2177,1180 2207,1210 2267.22,1210 P1.38
I2S_DO: P1.40 U1.65 | length 1453.3
  Top Layer w4: v1(1716,865) 1692,841 1692,398 1716.31,373.69 U1.65
  MidLayer1 w6: v1(1716,865) 1898,865 2077,1044 2163,1044 2267,1148 2267,1177 2301,1211 2368.22,1211 P1.40
I2S_WS: P1.35 U1.67 | length 1265.4
  Top Layer w4: v1(1699,881) 1676,858 1676,390 1711.99,354.01 U1.67
  MidLayer1 w6: v1(1699,881) 1878,881 2058,1061 2145,1061 2217.53,1133.53 P1.35
IO_6: P1.27 U1.27 | length 584.5
  Top Layer w6: U1.27 1855.71,747.71 1948,840 1948,1029.83 P1.27
IO_7: P1.28 U1.25 | length 703
  Top Layer w6: U1.25 1856.39,767.39 1930,841 1930,1028 1848,1110 1814,1110 1778,1146 1778,1220.78 P1.28
IO_8: P1.29 U1.23 | length 536.1
  Top Layer w6: U1.23 1850.08,787.08 1913,850 1913,1024.24 1850.46,1086.78 v1(1844,1086.78)
  Bottom Layer w6: v1(1844,1086.78) P1.29
IO_9: P1.8 U1.21 | length 1443.5
  Top Layer w6: U1.21 1829.76,806.76 v1(1843,820)
  MidLayer1 w6: P1.8 867.53,1210.31 867.53,1132.47 1322,678 1609,678 1737.76,806.76 1829.76,806.76 v1(1843,820)
IO_10: P1.10 U1.19 | length 1312.8
  Top Layer w6: U1.19 v1(1816,826.45)
  MidLayer1 w6: P1.10 967,1210.83 967,1063 1334,696 1602.1,696 1732.55,826.45 v1(1816,826.45)
IO_11: P1.37 U1.17 | length 671.6
  Top Layer w6: U1.17 v1(1878,846.13)
  MidLayer1 w6: v1(1878,846.13) 1916.13,846.13 2097,1027 2184.22,1027 P1.37
IO_12: P1.36 U1.7 | length 610.2
  Top Layer w6: U1.7 v1(1878.56,944.56)
  MidLayer1 w6: v1(1878.56,944.56) 2024,1090 2112,1090 2159,1137 2159,1201.78 P1.36
IO_13: P1.33 U1.30 | length 899.3
  Top Layer w4: U1.30 1521.18,718.18 v1(1532,729)
  MidLayer1 w4: v1(1532,729) 1552,749 1552,883 1774,1105 2062.22,1105 P1.33
IO_14: P1.32 U1.28 | length 874
  Top Layer w4: U1.28 1516.87,737.87 v1(1538,759)
  MidLayer1 w4: v1(1538,759) 1538,894 1762,1118 1945,1118 1967,1140 1967,1209.78 P1.32
IO_15: P1.31 U1.26 | length 793.3
  Top Layer w4: v1(1435.45,757.55) U1.26
  Bottom Layer w4: v1(1435.45,757.55) 1509.55,757.55 1815,1063 1920.22,1063 P1.31
IO_17: P1.26 U1.22 | length 673.7
  Top Layer w4: v1(1435.92,796.92) U1.22
  Bottom Layer w4: v1(1435.92,796.92) 1520.92,796.92 1657,933 1657,1199.78 P1.26
IO_18: P1.24 U1.20 | length 801.5
  Top Layer w4: U1.20 1524.61,816.61 1535,827 1535,869 1517,887 1427,887 1382,932 1382,1187 1402,1207 1564.22,1207 P1.24
IO_19: P1.22 U1.18 | length 696.7
  Top Layer w4: U1.18 1518.29,836.29 1524,842 1524,861 1513,872 1412,872 1369,915 1369,1192 1400,1223 1480.22,1223 P1.22
IO_20: P1.18 U1.16 | length 514.8
  Top Layer w4: P1.18 1357,1220.83 1357,905 1406.02,855.98 U1.16
IO_21: P1.16 U1.74 | length 1182.6
  Top Layer w4: v1(1239,512) 1239,397 1350.89,285.11 U1.74
  Bottom Layer w4: P1.16 1267,1210.83 1267,1104 1239,1076 v1(1239,512)
IO_22: P1.15 U1.72 | length 1048.9
  Top Layer w4: v1(1222,528) 1244,528 1256,516 1256,406 1357.2,304.8 U1.72
  Bottom Layer w4: P1.15 1222,1155.83 v1(1222,528)
IO_23: P1.13 U1.70 | length 1077.5
  Top Layer w4: v1(1206,544) 1249,544 1272,521 1272,419 1366.52,324.48 U1.70
  Bottom Layer w4: P1.13 1206,1071.83 v1(1206,544)
IO_24: P1.11 U1.68 | length 1105.5
  Top Layer w4: v1(1190,563) 1252,563 1290,525 1290,429 1374.83,344.17 U1.68
  Bottom Layer w4: P1.11 1190,987.83 v1(1190,563)
IO_25: P1.7 U1.66 | length 1177.8
  Top Layer w4: v1(1172,583) 1256,583 1310,529 1310,435 1381.15,363.85 U1.66
  Bottom Layer w4: P1.7 1172,805.83 v1(1172,583)
ISP_RX: TP3.1 U1.31 U7.21 | length 519
  Top Layer w4: U1.31 1998.66,708.34 v1(2123,584) ; TP3.1 v1(2158,529) 2183.82,529 2185.26,530.44 U7.21
  Bottom Layer w4: v1(2123,584) 2123,564 v1(2158,529)
ISP_TX: TP5.1 U1.29 U7.20 | length 505.8
  Top Layer w4: U1.29 2022.98,728.02 v1(2161,590) ; v1(2161.53,549.53) U7.20
  Bottom Layer w4: v1@2161,550.06 v1(2161,590)
LCD_CS: P4.7 U1.59 | length 1436.6
  Top Layer w4: P4.7 429.43,649 v1(466,649) ; v1(1721,432.75) U1.59
  Bottom Layer w4: v1(466,649) 622,649 838.25,432.75 v1(1721,432.75)
LCD_DC: P4.9 U1.55 | length 1436.9
  Top Layer w4: P4.9 429.49,689 v1(466,689) ; v1(1733.12,472.12) U1.55
  Bottom Layer w4: v1(466,689) 638,689 854.88,472.12 v1(1733.12,472.12)
LCD_RST: P4.8 U1.57 | length 1591.6
  Top Layer w4: v1(392,668.97) P4.8 ; U1.57 v1(1816.43,452.43)
  Bottom Layer w4: v1(392,668.97) 632.03,668.97 848.57,452.43 v1(1816.43,452.43)
LCD_WR: P4.10 U1.53 | length 1592.4
  Top Layer w4: v1(392,708.34) P4.10 ; U1.53 v1(1816.8,491.8)
  Bottom Layer w4: v1(392,708.34) 646.66,708.34 863.2,491.8 v1(1816.8,491.8)
NetC35_2: C35.2 R30.2 U7.5 U7.6 | length 346.4
  Top Layer w8: U7.5 U7.6 2356.01,441.26 C35.2 2410.27,372.73 2419,364 2465.46,364 2481,379.54 2481,448 2465.5,463.5 R30.2
NetDS3_A: DS3.A R43.2 | length 50.8
  Top Layer w6: DS3.A@2138,231.47 R43.2
NetJ3_2: J3.2 U7.4 | length 115.7
  Top Layer w4: v1(2273.84,421.84) U7.4 ; J3.2 v1(2288.4,366)
  Bottom Layer w4: v1(2273.84,421.84) 2288.4,407.28 v1(2288.4,366)
NetJ3_3: J3.3 U7.3 | length 156.7
  Top Layer w4: U7.3 2254.16,418.84 2267,406 2305,406 2305,405.8 2313.99,396.8 J3.3
NetJ4_23: J4.23 R38.1 | length 66.7
  Top Layer w8: R38.1 2454.59,550.86 J4.23
NetJ4_24: J4.24 R33.1 | length 74.4
  Top Layer w8: R33.1 2476.49,501.75 J4.24
NetL5_2: L5.2 U9.5 | length 78.5
  Top Layer w16: U9.5 2135.6,1053.17 L5.2
NetP1_23: P1.23 R23.2 | length 97.8
  Top Layer w10: R23.2 1617.53,1159.8 P1.23
NetP4_1: P4.1 R1.2 | length 65.3
  Top Layer w10: P4.1 468.83,531.17 474,526 R1.2
NetR30_1: R30.1 U7.9 | length 86.9
  Top Layer w6: U7.9 2363.61,510.16 R30.1
NetR43_1: R43.1 U9.3 | length 627.5
  Top Layer w6: R43.1 2138,349 2186,397 v1(2187,397)
  MidLayer1 w6: v1(2187,397) 2187,422 2210.4,445.4 v1(2210.4,912.63)
RESETN: C46.2 S1.2 T2.3 U1.1 | length 1138.4
  Top Layer w4: v1(1732,847) 1732,996 1739.61,1003.61 U1.1 ; T2.3 v1(1865.74,508.54) 1865.74,480.26 1896,450 1896,319 1951.92,263.08 2016.88,263.08 2016.88,293.88 2038.73,315.73 C46.2
  MidLayer1 w4: v1(1732,847) 1846,847 1865.74,827.26 v1(1865.74,508.54)
RTS: T1.1 T2.2 U7.19 | length 231.2
  Top Layer w4: T2.2 2072.02,579.4 2082.21,569.21 U7.19
SPI0_D0: P4.19 U1.32 | length 1128.2
  Top Layer w4: P4.19 1198.5,885.5 1385.5,698.5 U1.32
SPI0_D1: P4.18 U1.34 | length 1128.2
  Top Layer w4: P4.18 1194.18,865.82 1381.19,678.81 U1.34
SPI0_D2: P4.17 U1.36 | length 1128.2
  Top Layer w4: P4.17 1189.87,846.13 1376.87,659.13 U1.36
SPI0_D3: P4.16 U1.38 | length 1128.2
  Top Layer w4: P4.16 1184.55,826.45 1371.56,639.44 U1.38
SPI0_D4: P4.15 U1.40 | length 1128.2
  Top Layer w4: P4.15 1178.24,806.76 1365.24,619.76 U1.40
SPI0_D5: P4.14 U1.42 | length 1128.2
  Top Layer w4: P4.14 1172.92,787.08 1359.93,600.07 U1.42
SPI0_D6: P4.13 U1.44 | length 1128.2
  Top Layer w4: P4.13 1166.61,767.39 1353.61,580.39 U1.44
SPI0_D7: P4.12 U1.46 | length 1128.2
  Top Layer w4: P4.12 1160.29,747.71 1347.3,560.7 U1.46
TF_CLK: J1.5 R20.2 R23.1 U1.62 | length 1842.4
  Top Layer w4: R20.2 646.68,428.93 J1.5 646.67,314.33 657,304 823,304 922.22,403.22 v1(1037,403.22) ; v1(1431,403.22) U1.62 1516.22,403.22 1612,499 1612,931 1515.27,1027.73 R23.1
  Bottom Layer w4: v1(1037,403.22) v1(1431,403.22)
TF_CS: J1.2 R28.2 U1.75 | length 1235.9
  Top Layer w4: J1.2 v1(776.59,395) R28.2@776.59,473.59 ; v1(950,306) 1056,200 1619,200 1694.27,275.27 U1.75
  Bottom Layer w4: v1(776.59,395) 865.59,306 v1(950,306)
TF_MISO: J1.7 P1.21 R29.2 U1.64 | length 2204.7
  Top Layer w4: R29.2 603.16,417.16 560.05,374.05 J1.7 560.05,307.95 573,295 835.08,295 923.62,383.54 v1(1047,383.54) ; v1(1440,383.54) U1.64 1517.54,383.54 1626,492 1626,1108 1656,1138 1656,1184 1638,1202 1601,1202 1559.31,1160.31 P1.21
  Bottom Layer w4: v1(1047,383.54) v1(1440,383.54)
TF_MOSI: J1.3 P1.19 R27.2 U1.60 | length 1867.2
  Top Layer w4: R27.2@733.28,473.81 J1.3 733.28,322.72 744,312 789,312 798,321 798,379 809,390 891,390 v1(919,418) ; v1(1406,418) 1410.91,422.91 U1.60 1520.91,422.91 1598,500 1598,927 1417.53,1107.47 P1.19
  Bottom Layer w4: v1(919,418) v1(1406,418)
VCC1V8: R36.2 U1.3 | length 75.1
  Top Layer w8: U1.3 R36.2@1851.2,983.93
VCC3V3: C1.2 C2.1 C37.2 C43.1 J1.4 P1.1 P1.17 P4.4 R6.2 R17.2 R20.1 R27.1 R28.1 R29.1 R37.2 R38.2 U3.2 | length 4624.8
  Top Layer w8: J1.4 689.97,387.97 712,410 712,507.73 ; 1268,1209.83 1268,1294 1284.31,1310.31 1761,1310.31 ; R37.2 1884.71,1017.73 1761,1141.44 1761,1310.31 ; R38.2 2328.27,622 2171,622 1967.53,825.47 1967.53,1284.47 1941.69,1310.31 1761,1310.31
  Top Layer w10: P4.4 466,590.23 ; R6.2 R17.2 R29.1 R20.1@652.37,507.73 ; R20.1 712,507.73 R27.1 R28.1
  Top Layer w14: 466,590.23 477,590.23 497.96,569.27 C37.2 C1.2 R17.2
  Top Layer w20: P1.1 567.06,1209.83 1268,1209.83 P1.17 ; C1.2 C2.1 625.73,569.27 646.4,548.6 U3.2 799.6,548.6 807,556 807,643 v1(778,672)
  Bottom Layer w20: P1.1 517.53,932.47 v1(778,672)
VCCUSB: C3.1 C25.1 C34.2 C53.2 J3.1 P1.2 P1.4 P4.2 U1.2 U1.4 U3.3 U5.3 U7.7 U7.8 U8.3 U9.1 | length 5119.2
  Top Layer w8: U7.8 U7.7 2348.21,470.79 v1(2360,459) 2393.75,425.25 C34.2
  Top Layer w14: v1(384.14,550.86) P4.2 ; v1(481,621) 493,633 614,633 661,586 U3.3 ; C3.1@1411.04,993.77 C3.1@1414.23,993.77 ; U1.4 1433.91,974.09 C3.1@1414.23,993.77 ; U1.2 C3.1@1414.23,993.77
  Top Layer w16: C53.2 2135.69,812.32 2158,790 U5.3 U8.3
  Top Layer w20: C3.1 v1(1408,1025)
  Top Layer w25: v1@2096,888.73 C25.1 2096.27,856 C53.2@2135.6,856
  Top Layer w30: C53.2@2135.6,851.09 C53.2@2135.6,856 ; U9.1 C53.2@2135.6,856 ; C53.2 C53.2@2135.6,856
  MidLayer1 w30: v1(2095.73,889) 2095.73,435.42 v1(2199.58,331.58)
  Bottom Layer w10: v1(2231.2,331.58) 2231.2,416.2 2274,459 v1(2360,459)
  Bottom Layer w14: 349,621 v1(481,621) ; v1(384.14,550.86) 348,587 348,1006 458,1116 458,1200.78 P1.2
  Bottom Layer w25: P1.4 666.22,1309 1367.53,1309 ; v1(1408,1025) 1367.53,1065.47 1367.53,1309 ; v1(2095.73,889) 2095.73,1030.27 2068,1058 2068,1282 2041,1309 1367.53,1309
  Bottom Layer w30: P1.2 P1.4
VDD1V2: C45.2 C47.1 J4.10 U5.2 | length 165.8
  Top Layer w10: 2374,827 2443.73,827 ; C45.2 2443.73,822.67 2459.64,806.76 J4.10
VDDIO67: C4.2 C44.2 J4.11 P4.5 P4.11 R36.1 R37.1 R39.2 R40.2 U1.5 | length 1423.2
  Top Layer w6: U1.5 v1(1823,964.2) 1877.2,964.2 1884.73,971.73 R36.1
  Top Layer w10: P4.5 379.09,609.91 365,624 365,713 v1(380.02,728.02) P4.11 506.98,728.02 516,719 C4.2 ; v1(2386,884) R39.2 ; v1(2388,960) R40.2 ; v1(2433,797) 2443.73,786.27 C44.2@2443.73,781 ; C44.2@2443.73,787 2443.81,787.08 J4.11
  MidLayer1 w10: v1(2388,960) 2364,936 2364,906 v1(2386,884) 2433,837 v1(2433,797)
  Bottom Layer w6: v1(1823,964.2) 1926.8,964.2 2036,855 2185,855 2214,884 v1(2386,884)
pads on no net: J1.1 J1.8 J3.4 J4.1 M2.0 P4.6 P4.21 P4.22 P4.23 P4.24 U7.1 U7.10 U7.11 U7.12 U7.13 U7.14 U7.15 U7.16 U7.17 U7.18 U7.22 U7.24

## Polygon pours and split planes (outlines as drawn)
GND on Bottom Layer "t" (solid, remove dead copper, pour order 0): 149.81,1385.81 154.81,1380.81 2774.81,1380.81 2774.81,209.81 2702.81,137.81 2694.81,145.81 180.81,145.81
GND on Top Layer "t" (solid, remove dead copper, pour order 2): 163.18,1376.31 168.18,1381.31 2785.18,1381.31 2785.18,218.31 2706.18,139.31 2698.18,147.31 173.18,147.31
VDDIO67 on MidLayer1 "t" (solid, remove dead copper, pour order 4): 163,1383 2713,1383 2790,1306 2774,1290 2774,162 155,162 151,158
GND on GND (split plane): 2637.5,1327.72 2645.98,1326.61 2654.34,1324.75 2662.5,1322.18 2670.41,1318.9 2678,1314.95 2685.21,1310.35 2692,1305.14 2698.31,1299.36 2704.1,1293.05 2709.31,1286.26 2713.91,1279.04 2717.86,1271.45 2721.13,1263.55 2723.71,1255.38 2725.56,1247.03 2726.68,1238.54 2727.02,1230.63 2726.96,1229.99 2726.96,285.11 2727.02,284.48 2726.68,276.56 2725.56,268.07 2723.71,259.72 2721.13,251.56 2717.86,243.65 2713.91,236.06 2709.31,228.84 2704.1,222.05 2698.31,215.74 2692,209.96 2685.21,204.75 2678,200.15 2670.41,196.2 2662.5,192.92 2654.34,190.35 2645.98,188.5 2637.5,187.38 2629.58,187.03 2628.94,187.1 1491,187.1 1491,278 1203,278 1203,187.1 306.11,187.1 305.48,187.03 297.56,187.38 289.07,188.5 280.72,190.35 272.56,192.92 264.65,196.2 257.06,200.15 249.84,204.75 243.05,209.96 236.74,215.74 230.96,222.05 225.75,228.84 221.15,236.06 217.2,243.65 213.92,251.56 211.35,259.72 209.5,268.07 208.38,276.56 208.03,284.48 208.1,285.11 208.1,1229.99 208.03,1230.63 208.38,1238.54 209.5,1247.03 211.35,1255.38 213.92,1263.55 217.2,1271.45 221.15,1279.04 225.75,1286.26 230.96,1293.05 236.74,1299.36 243.05,1305.14 249.84,1310.35 257.06,1314.95 264.65,1318.9 272.56,1322.18 280.72,1324.75 289.07,1326.61 297.56,1327.72 305.48,1328.07 306.11,1328.01 2628.94,1328.01 2629.58,1328.07

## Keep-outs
Keep-Out Layer:
  circle w5: c2609.26,1210.31 r54.13
  circle w5: c2609.26,304.8 r54.13
  circle w5: c325.8,304.8 r54.13
  circle w5: c325.8,1210.31 r54.13
  lines w5: 188,285.11 ccw(c306.11,285.11) 306.11,167 886.82,167 2048.24,167 2628.94,167 ccw(c2628.94,285.11) 2747.06,285.11 2747.06,1229.99 ccw(c2628.94,1229.99) 2628.94,1348.1 306.11,1348.1 ccw(c306.11,1229.99) 188,1229.99 188,285.11

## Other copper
Top Layer:
  rectangle net VCCUSB: 2186,320 2270,353
MidLayer1:
  rectangle net VCCUSB: 2186,320 2250,353
GND (plane layer: these items are gaps in the copper):
  rectangle: 1203,167.61 1491,278

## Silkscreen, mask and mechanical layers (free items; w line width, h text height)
Top Overlay:
  text "BAT" at 2472,1064 h55.12
  text "-" at 2291,1010 h70
  text "-" at 2302,1010 h70
  text "+" at 2464,1007 h70
  text "AIRV" at 535,957 h150
  text "What will you make?" at 487.35,858 h50
  text "20190603 V2.0" at 541,803 h50
  text "LCD" at 496,703 h55.12 r90
  text "DVP" at 2472.59,620.33 h55.12 r90
  text "T" at 2101,598 h40
  text "R" at 2131,533 h40
  text "G" at 2095.73,454 h40
  text "TF CARD" at 583,410 h55.12
  text "BOOT" at 2052.7,393 h50
  text "PWR" at 2259,371 h55.12
  text "RST" at 1893.7,172 h50
  text "CHRG" at 2041,172 h50
Bottom Overlay:
  lines w5: 467.53,1010.31 2467.22,1010.31 ; 467.53,1110.31 2467.22,1110.31 ; 567.53,910.31 567.53,1310.31 ; 667.53,910.31 667.53,1310.31 ; 767.53,910.31 767.53,1310.31 ; 867.53,910.31 867.53,1310.31 ; 967.53,910.31 967.53,1310.31 ; 1067.53,910.31 1067.53,1310.31 ; 1167.53,910.31 1167.53,1310.31 ; 1267.53,910.31 1267.53,1310.31 ; 1367.53,907.16 1367.53,1310.31 ; 1467.53,910.31 1467.53,1310.31 ; 1567.53,910.31 1567.53,1310.31 ; 1667.53,910.31 1667.53,1310.31 ; 1767.53,910.31 1767.53,1310.31 ; 1867.53,910.31 1867.53,1310.31 ; 1967.53,910.31 1967.53,1310.31 ; 2067.53,910.31 2067.53,1310.31 ; 2167.53,910.31 2167.53,1310.31 ; 2267.53,812 2267.53,710.31 2367.53,710.31 ; 2267.53,1310.31 2267.53,810.31 2467.27,810.31 ; 2367.53,1310.31 2367.53,710.31 ; 2467.22,907.16 467.53,907.16 467.53,1310.31 2467.53,1310.31 ; 2467.53,900 2467.53,1310.31 ; 2367.53,710.31 2467.53,710.31 2467.53,1310.31
  text "21" at 1219,1031.86 h55.12 r315
  text "19" at 1521.82,1031.06 h55.12 r315
  text "18" at 1621.95,1031.06 h55.12 r315
  text "17" at 1721.59,1030.89 h55.12 r315
  text "14" at 2021.89,1030.92 h55.12 r315
  text "12" at 2222,1031 h55.12 r315
  text "35" at 1023.62,1029.84 h55.12 r315
  text "20" at 1324.23,1029.71 h55.12 r315
  text "5V" at 528,1027.39 h55.12 r315
  text "5V" at 628.13,1027.39 h55.12 r315
  text "TX1" at 833,1019.21 h55.12 r315
  text "RX1" at 933.9,1018.22 h55.12 r315
  text "GND" at 740,1015.35 h50 r315
  text "SCL" at 1839,1015.14 h55.12 r315
  text "GND" at 1141,1010.76 h55.12 r315
  text "GND" at 1440,1010.76 h55.12 r315
  text "GND" at 1942,1010.76 h55.12 r315
  text "GND" at 2142,1010.76 h55.12 r315
  text "16" at 1926,929.46 h55.12 r315
  text "15" at 2025,929.36 h55.12 r315
  text "13" at 2122,929.46 h55.12 r315
  text "MI" at 1522,929 h55.12 r315
  text "33" at 2225,928.3 h55.12 r315
  text "34" at 2427,928.33 h55.12 r315
  text "25" at 824,927.94 h55.12 r315
  text "24" at 1024.34,927.86 h55.12 r315
  text "23" at 1124.66,928.03 h55.12 r315
  text "22" at 1227,927.94 h55.12 r315
  text "32" at 2322,928 h55.12 r315
  text "MO" at 1432,920 h55.12 r315
  text "3V3" at 537,913 h60 r315
  text "3V3" at 1338,913 h60 r315
  text "CLK" at 1637,913 h55.12 r315
  text "SDA" at 642,911 h55.12 r315
  text "SDA" at 1842,911 h55.12 r315
  text "SCL" at 740,910 h60 r315
  text "GND" at 943,909.12 h55.12 r315
  text "GND" at 1742,909 h55.12 r315
  text "11" at 2320,834 h55.12 r315
  text "GND" at 2443,809 h55.12 r315
  text "BAT" at 2437,715 h55.12 r315
  text "GND" at 2342,712 h55.12 r315
  text "Designed by Yuan" at 649,187 h86.61 r315
Top Solder:
  circle w63.98: c325.8,304.8 r85.83
  circle w63.98: c325.8,1210.31 r85.83
  circle w63.98: c2609.26,1210.31 r85.83
  circle w63.98: c2609.26,304.8 r85.83
Bottom Solder:
  circle w63.98: c325.8,304.8 r85.83
  circle w63.98: c325.8,1210.31 r85.83
  circle w63.98: c2609.26,1210.31 r85.83
  circle w63.98: c2609.26,304.8 r85.83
